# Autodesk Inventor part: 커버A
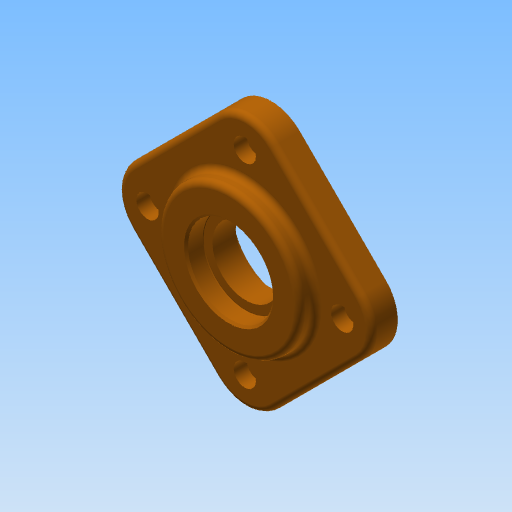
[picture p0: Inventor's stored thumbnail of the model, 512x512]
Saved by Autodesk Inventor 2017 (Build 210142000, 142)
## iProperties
Created: 2013-01
Part Number: 커버A
Document SubType Name: Modeling
Density: 1 g/cm^3
Material: 알루미늄 6061
Designer: mdu
Appearance: 주황색
Author: mdu
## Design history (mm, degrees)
sketch "스케치1"
  geometry: L1 (56.569, -14.142)-(14.142, -56.569) reference; L2 (-14.142, -56.569)-(-56.569, -14.142) reference; L3 (-56.569, 14.142)-(-14.142, 56.569) reference; L4 (14.142, 56.569)-(56.569, 14.142) reference; C1 r 31 at (0, 0) reference; A1 r 20 centre (0, -42.426) between (-14.142, -56.569) and (14.142, -56.569) reference; A2 r 20 centre (-42.426, 0) between (-56.569, 14.142) and (-56.569, -14.142) reference; A3 r 20 centre (0, 42.426) between (14.142, 56.569) and (-14.142, 56.569) reference; A4 r 20 centre (42.426, 0) between (56.569, -14.142) and (56.569, 14.142) reference; 1 further point
extrude "돌출1" new body sketch "스케치1" distance "d0" = 13; taper "d1" = 0 deg
sketch "스케치2"
  geometry: C1 r 35 at (0, 0); 1 further point
  constraints: 1 centre point, 1 coincident
  dimensions: "d2" = 70 diameter of C1
extrude "돌출2" join sketch "스케치2" distance "d3" = 8; taper "d4" = 0 deg
fillet "모깎기1" dims "d5" = 3
sketch "스케치3"
  geometry: C1 r 2.458 at (0, 48) reference; 1 further point
hole "구멍1" sketch "스케치3" at (0, 48) diameter "d6" = 6.6; stored, may be unused: countersink angle "d10" = 90 deg, drill point angle "d12" = 118 deg; dims "d7" = 6, "d8" = 11, "d9" = 6.5, "d11" = 8
hole "구멍2" diameter "d18" = 33; stored, may be unused: countersink angle "d22" = 90 deg, drill point angle "d24" = 118 deg; dims "d16" = 10, "d17" = 10, "d19" = 6, "d20" = 42, "d21" = 8.5, "d23" = 8
sketch "스케치4"
  geometry: C1 r 31 at (0, 0) reference; 1 further point
extrude "돌출3" join sketch "스케치4" distance "d25" = 6; taper "d26" = 0 deg
hole "구멍3" diameter "d29" = 50; stored, may be unused: countersink angle "d33" = 90 deg, drill point angle "d35" = 0 deg; dims "d27" = 10, "d28" = 10, "d30" = 6, "d31" = 42, "d32" = 8.5, "d34" = 7
fillet "모깎기2" dims "d36" = 3, "d37" = 0.4
chamfer "모따기1" distance "d38" = 1; stored, may be unused: second distance "d39" = 2, angle "d40" = 45 deg
node "솔리드1"
pattern_circular "원형 패턴1" dims angle "d14" = 360 deg
node "참조1"
node "참조2"
node "참조3"
node "참조4"
node "참조5"
node "참조6"
node "참조7"
node "참조8"
node "참조9"
node "참조10"
node "참조11"
